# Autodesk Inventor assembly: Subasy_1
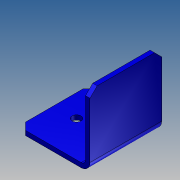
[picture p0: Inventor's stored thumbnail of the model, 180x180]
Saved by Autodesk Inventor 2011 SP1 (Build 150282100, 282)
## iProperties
Created: 2013-10
Part Number: Subasy_1
Document SubType Name: Assembly
Designer: Ralph.Nemitz
Mass: 15.4677 g
Surface Area: 107.284 cm^2
Volume: 15.4677 cm^3
Density: 1 g/cm^3
Author: Ralph.Nemitz
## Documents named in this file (2)
- C:\Users\Ralph.Nemitz\Documents\Inventor\Regeltest\Subassy_1.iam
- C:\Users\Ralph.Nemitz\Documents\Inventor\Regeltest\bracket.ipt
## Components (1 placed, 1 different names)
1. bracket:1
